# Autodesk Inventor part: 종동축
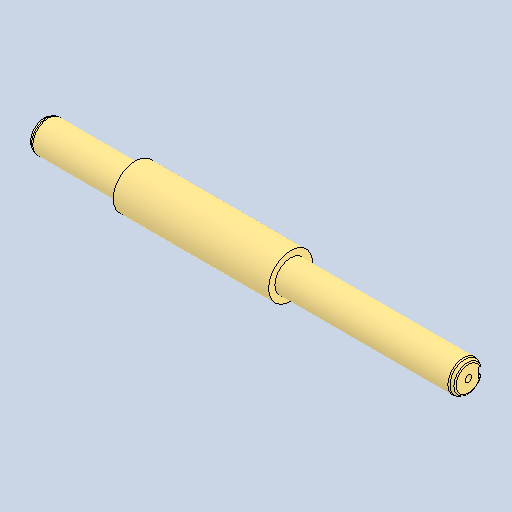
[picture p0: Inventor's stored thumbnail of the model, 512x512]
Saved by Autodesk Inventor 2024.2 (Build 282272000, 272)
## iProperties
Created: 2026-01
Part Number: 종동축
Material: 강철, 탄소
Document SubType Name: Modeling
Designer: home
Density: 7.85 g/cm^3
Appearance: 기본값
Author: jhkim
Sending System: Autodesk Inventor 2026
Preprocessor: ST-DEVELOPER v20.1
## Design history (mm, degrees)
feature "솔리드1"
node "솔리드2"
